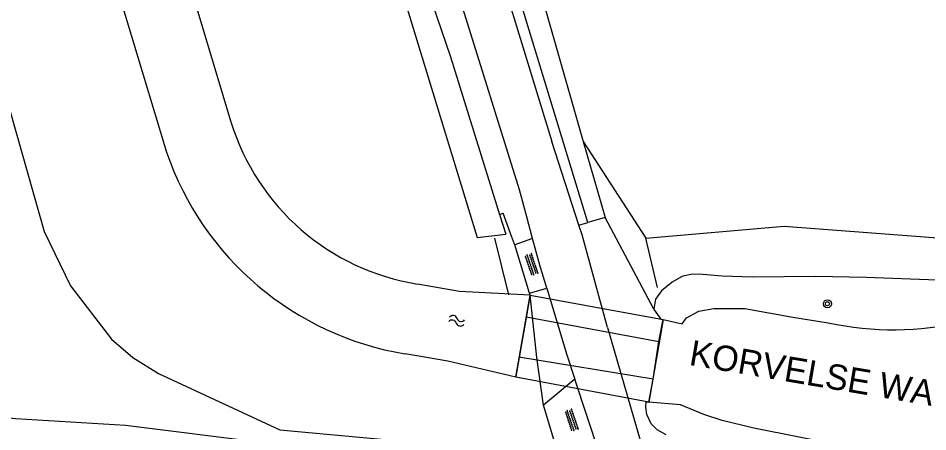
# Model space of a CAD drawing. Extents: x 135999 to 138000, y 396000 to 398501.
# Drawn here: x 136678.3 to 136768.1, y 396574.3 to 396615.1 of the extents above; entities that cross this region are included whole.
import ezdxf

# ---------------------------------------------------------------- set-up
doc = ezdxf.new("R2010")
doc.units = 0
for name, color, linetype in [('gg-afsc-draadraster', 7, 'Continuous'), ('gg-afsc-erfafscheiding', 7, 'Continuous'), ('gg-afsc-faunaraster', 7, 'Continuous'), ('gg-afsc-hekwerk', 7, 'Continuous'), ('gg-afsc-muur', 7, 'Continuous'), ('gg-anno-naam water', 7, 'Continuous'), ('gg-knt-bronhoudergrens', 7, 'Continuous'), ('gg-knt-onverhard', 7, 'Continuous'), ('gg-knt-verharding', 7, 'Continuous'), ('gg-kntw-beschoeiing', 7, 'Continuous'), ('gg-kntw-bovenkant insteek waterloop', 7, 'Continuous'), ('gg-kntw-waterlijn', 7, 'Continuous'), ('gg-kwrk-duiker nz buis', 7, 'Continuous'), ('gg-kwrk-duiker nz vlak', 7, 'Continuous'), ('gt-grn-groengrens', 7, 'Continuous'), ('gt-symb-boom', 7, 'Continuous'), ('gt-symb-overige verharding', 7, 'Continuous'), ('gt-symb-watersymbool', 7, 'Continuous'), ('gx-grn-maaiveld', 7, 'Continuous')]:
    doc.layers.add(name, color=color, linetype=linetype)

# ---------------------------------------------------------------- blocks, each defined once
blk = doc.blocks.new('gt0-OVH')
at = {"layer": 'gt-symb-overige verharding'}
for points in [[(-0.972, 0.298), (-0.967, 0.308), (-0.965, 0.319), (-0.966, 0.33), (-0.971, 0.34), (-0.978, 0.348), (-0.988, 0.353), (-0.999, 0.355), (-1.01, 0.354), (-1.02, 0.349), (-1.028, 0.342), (-1.033, 0.332), (-1.035, 0.321), (-1.034, 0.31), (-1.029, 0.3), (-1.022, 0.292), (-1.012, 0.287), (-1.001, 0.285), (-0.99, 0.286), (-0.98, 0.291)], [(-0.872, 0.106), (-0.867, 0.116), (-0.865, 0.126), (-0.866, 0.137), (-0.871, 0.147), (-0.878, 0.156), (-0.888, 0.161), (-0.899, 0.163), (-0.91, 0.162), (-0.92, 0.157), (-0.928, 0.15), (-0.933, 0.14), (-0.935, 0.129), (-0.934, 0.118), (-0.929, 0.108), (-0.922, 0.1), (-0.912, 0.095), (-0.901, 0.092), (-0.89, 0.094), (-0.88, 0.098)], [(-0.772, 0.298), (-0.767, 0.308), (-0.765, 0.319), (-0.766, 0.33), (-0.771, 0.34), (-0.778, 0.348), (-0.788, 0.353), (-0.799, 0.355), (-0.81, 0.354), (-0.82, 0.349), (-0.828, 0.342), (-0.833, 0.332), (-0.835, 0.321), (-0.834, 0.31), (-0.829, 0.3), (-0.822, 0.292), (-0.812, 0.287), (-0.801, 0.285), (-0.79, 0.286), (-0.78, 0.291)], [(-0.672, 0.106), (-0.667, 0.116), (-0.665, 0.126), (-0.666, 0.137), (-0.671, 0.147), (-0.678, 0.156), (-0.688, 0.161), (-0.699, 0.163), (-0.71, 0.162), (-0.72, 0.157), (-0.728, 0.15), (-0.733, 0.14), (-0.735, 0.129), (-0.734, 0.118), (-0.729, 0.108), (-0.722, 0.1), (-0.712, 0.095), (-0.701, 0.092), (-0.69, 0.094), (-0.68, 0.098)], [(-0.572, 0.298), (-0.567, 0.308), (-0.565, 0.319), (-0.566, 0.33), (-0.571, 0.34), (-0.578, 0.348), (-0.588, 0.353), (-0.599, 0.355), (-0.61, 0.354), (-0.62, 0.349), (-0.628, 0.342), (-0.633, 0.332), (-0.635, 0.321), (-0.634, 0.31), (-0.629, 0.3), (-0.622, 0.292), (-0.612, 0.287), (-0.601, 0.285), (-0.59, 0.286), (-0.58, 0.291)], [(-0.472, 0.106), (-0.467, 0.116), (-0.465, 0.126), (-0.466, 0.137), (-0.471, 0.147), (-0.478, 0.156), (-0.488, 0.161), (-0.499, 0.163), (-0.51, 0.162), (-0.52, 0.157), (-0.528, 0.15), (-0.533, 0.14), (-0.535, 0.129), (-0.534, 0.118), (-0.529, 0.108), (-0.522, 0.1), (-0.512, 0.095), (-0.501, 0.092), (-0.49, 0.094), (-0.48, 0.098)], [(-0.372, 0.298), (-0.367, 0.308), (-0.365, 0.319), (-0.366, 0.33), (-0.371, 0.34), (-0.378, 0.348), (-0.388, 0.353), (-0.399, 0.355), (-0.41, 0.354), (-0.42, 0.349), (-0.428, 0.342), (-0.433, 0.332), (-0.435, 0.321), (-0.434, 0.31), (-0.429, 0.3), (-0.422, 0.292), (-0.412, 0.287), (-0.401, 0.285), (-0.39, 0.286), (-0.38, 0.291)], [(-0.272, 0.106), (-0.267, 0.116), (-0.265, 0.126), (-0.266, 0.137), (-0.271, 0.147), (-0.278, 0.156), (-0.288, 0.161), (-0.299, 0.163), (-0.31, 0.162), (-0.32, 0.157), (-0.328, 0.15), (-0.333, 0.14), (-0.335, 0.129), (-0.334, 0.118), (-0.329, 0.108), (-0.322, 0.1), (-0.312, 0.095), (-0.301, 0.092), (-0.29, 0.094), (-0.28, 0.098)], [(-0.172, 0.298), (-0.167, 0.308), (-0.165, 0.319), (-0.166, 0.33), (-0.171, 0.34), (-0.178, 0.348), (-0.188, 0.353), (-0.199, 0.355), (-0.21, 0.354), (-0.22, 0.349), (-0.228, 0.342), (-0.233, 0.332), (-0.235, 0.321), (-0.234, 0.31), (-0.229, 0.3), (-0.222, 0.292), (-0.212, 0.287), (-0.201, 0.285), (-0.19, 0.286), (-0.18, 0.291)], [(-0.072, 0.106), (-0.067, 0.116), (-0.065, 0.126), (-0.066, 0.137), (-0.071, 0.147), (-0.078, 0.156), (-0.088, 0.161), (-0.099, 0.163), (-0.11, 0.162), (-0.12, 0.157), (-0.128, 0.15), (-0.133, 0.14), (-0.135, 0.129), (-0.134, 0.118), (-0.129, 0.108), (-0.122, 0.1), (-0.112, 0.095), (-0.101, 0.092), (-0.09, 0.094), (-0.08, 0.098)], [(0.028, 0.298), (0.033, 0.308), (0.035, 0.319), (0.034, 0.33), (0.029, 0.34), (0.022, 0.348), (0.012, 0.353), (0.001, 0.355), (-0.01, 0.354), (-0.02, 0.349), (-0.028, 0.342), (-0.033, 0.332), (-0.035, 0.321), (-0.034, 0.31), (-0.029, 0.3), (-0.022, 0.292), (-0.012, 0.287), (-0.001, 0.285), (0.01, 0.286), (0.02, 0.291)], [(0.128, 0.106), (0.133, 0.116), (0.135, 0.126), (0.134, 0.137), (0.129, 0.147), (0.122, 0.156), (0.112, 0.161), (0.101, 0.163), (0.09, 0.162), (0.08, 0.157), (0.072, 0.15), (0.067, 0.14), (0.065, 0.129), (0.066, 0.118), (0.071, 0.108), (0.078, 0.1), (0.088, 0.095), (0.099, 0.092), (0.11, 0.094), (0.12, 0.098)], [(0.228, 0.298), (0.233, 0.308), (0.235, 0.319), (0.234, 0.33), (0.229, 0.34), (0.222, 0.348), (0.212, 0.353), (0.201, 0.355), (0.19, 0.354), (0.18, 0.349), (0.172, 0.342), (0.167, 0.332), (0.165, 0.321), (0.166, 0.31), (0.171, 0.3), (0.178, 0.292), (0.188, 0.287), (0.199, 0.285), (0.21, 0.286), (0.22, 0.291)], [(0.328, 0.106), (0.333, 0.116), (0.335, 0.126), (0.334, 0.137), (0.329, 0.147), (0.322, 0.156), (0.312, 0.161), (0.301, 0.163), (0.29, 0.162), (0.28, 0.157), (0.272, 0.15), (0.267, 0.14), (0.265, 0.129), (0.266, 0.118), (0.271, 0.108), (0.278, 0.1), (0.288, 0.095), (0.299, 0.092), (0.31, 0.094), (0.32, 0.098)], [(0.428, 0.298), (0.433, 0.308), (0.435, 0.319), (0.434, 0.33), (0.429, 0.34), (0.422, 0.348), (0.412, 0.353), (0.401, 0.355), (0.39, 0.354), (0.38, 0.349), (0.372, 0.342), (0.367, 0.332), (0.365, 0.321), (0.366, 0.31), (0.371, 0.3), (0.378, 0.292), (0.388, 0.287), (0.399, 0.285), (0.41, 0.286), (0.42, 0.291)], [(0.528, 0.106), (0.533, 0.116), (0.535, 0.126), (0.534, 0.137), (0.529, 0.147), (0.522, 0.156), (0.512, 0.161), (0.501, 0.163), (0.49, 0.162), (0.48, 0.157), (0.472, 0.15), (0.467, 0.14), (0.465, 0.129), (0.466, 0.118), (0.471, 0.108), (0.478, 0.1), (0.488, 0.095), (0.499, 0.092), (0.51, 0.094), (0.52, 0.098)], [(0.628, 0.298), (0.633, 0.308), (0.635, 0.319), (0.634, 0.33), (0.629, 0.34), (0.622, 0.348), (0.612, 0.353), (0.601, 0.355), (0.59, 0.354), (0.58, 0.349), (0.572, 0.342), (0.567, 0.332), (0.565, 0.321), (0.566, 0.31), (0.571, 0.3), (0.578, 0.292), (0.588, 0.287), (0.599, 0.285), (0.61, 0.286), (0.62, 0.291)], [(0.728, 0.106), (0.733, 0.116), (0.735, 0.126), (0.734, 0.137), (0.729, 0.147), (0.722, 0.156), (0.712, 0.161), (0.701, 0.163), (0.69, 0.162), (0.68, 0.157), (0.672, 0.15), (0.667, 0.14), (0.665, 0.129), (0.666, 0.118), (0.671, 0.108), (0.678, 0.1), (0.688, 0.095), (0.699, 0.092), (0.71, 0.094), (0.72, 0.098)], [(0.828, 0.298), (0.833, 0.308), (0.835, 0.319), (0.834, 0.33), (0.829, 0.34), (0.822, 0.348), (0.812, 0.353), (0.801, 0.355), (0.79, 0.354), (0.78, 0.349), (0.772, 0.342), (0.767, 0.332), (0.765, 0.321), (0.766, 0.31), (0.771, 0.3), (0.778, 0.292), (0.788, 0.287), (0.799, 0.285), (0.81, 0.286), (0.82, 0.291)], [(0.928, 0.106), (0.933, 0.116), (0.935, 0.126), (0.934, 0.137), (0.929, 0.147), (0.922, 0.156), (0.912, 0.161), (0.901, 0.163), (0.89, 0.162), (0.88, 0.157), (0.872, 0.15), (0.867, 0.14), (0.865, 0.129), (0.866, 0.118), (0.871, 0.108), (0.878, 0.1), (0.888, 0.095), (0.899, 0.092), (0.91, 0.094), (0.92, 0.098)], [(1.028, 0.298), (1.033, 0.308), (1.035, 0.319), (1.034, 0.33), (1.029, 0.34), (1.022, 0.348), (1.012, 0.353), (1.001, 0.355), (0.99, 0.354), (0.98, 0.349), (0.972, 0.342), (0.967, 0.332), (0.965, 0.321), (0.966, 0.31), (0.971, 0.3), (0.978, 0.292), (0.988, 0.287), (0.999, 0.285), (1.01, 0.286), (1.02, 0.291)], [(-0.972, -0.142), (-0.967, -0.132), (-0.965, -0.121), (-0.966, -0.11), (-0.971, -0.1), (-0.978, -0.092), (-0.988, -0.087), (-0.999, -0.085), (-1.01, -0.086), (-1.02, -0.091), (-1.028, -0.098), (-1.033, -0.108), (-1.035, -0.119), (-1.034, -0.13), (-1.029, -0.14), (-1.022, -0.148), (-1.012, -0.153), (-1.001, -0.155), (-0.99, -0.154), (-0.98, -0.149)], [(-0.872, -0.334), (-0.867, -0.324), (-0.865, -0.314), (-0.866, -0.303), (-0.871, -0.293), (-0.878, -0.284), (-0.888, -0.279), (-0.899, -0.277), (-0.91, -0.278), (-0.92, -0.283), (-0.928, -0.29), (-0.933, -0.3), (-0.935, -0.311), (-0.934, -0.322), (-0.929, -0.332), (-0.922, -0.34), (-0.912, -0.345), (-0.901, -0.348), (-0.89, -0.346), (-0.88, -0.342)], [(-0.772, -0.142), (-0.767, -0.132), (-0.765, -0.121), (-0.766, -0.11), (-0.771, -0.1), (-0.778, -0.092), (-0.788, -0.087), (-0.799, -0.085), (-0.81, -0.086), (-0.82, -0.091), (-0.828, -0.098), (-0.833, -0.108), (-0.835, -0.119), (-0.834, -0.13), (-0.829, -0.14), (-0.822, -0.148), (-0.812, -0.153), (-0.801, -0.155), (-0.79, -0.154), (-0.78, -0.149)], [(-0.672, -0.334), (-0.667, -0.324), (-0.665, -0.314), (-0.666, -0.303), (-0.671, -0.293), (-0.678, -0.284), (-0.688, -0.279), (-0.699, -0.277), (-0.71, -0.278), (-0.72, -0.283), (-0.728, -0.29), (-0.733, -0.3), (-0.735, -0.311), (-0.734, -0.322), (-0.729, -0.332), (-0.722, -0.34), (-0.712, -0.345), (-0.701, -0.348), (-0.69, -0.346), (-0.68, -0.342)], [(-0.572, -0.142), (-0.567, -0.132), (-0.565, -0.121), (-0.566, -0.11), (-0.571, -0.1), (-0.578, -0.092), (-0.588, -0.087), (-0.599, -0.085), (-0.61, -0.086), (-0.62, -0.091), (-0.628, -0.098), (-0.633, -0.108), (-0.635, -0.119), (-0.634, -0.13), (-0.629, -0.14), (-0.622, -0.148), (-0.612, -0.153), (-0.601, -0.155), (-0.59, -0.154), (-0.58, -0.149)], [(-0.472, -0.334), (-0.467, -0.324), (-0.465, -0.314), (-0.466, -0.303), (-0.471, -0.293), (-0.478, -0.284), (-0.488, -0.279), (-0.499, -0.277), (-0.51, -0.278), (-0.52, -0.283), (-0.528, -0.29), (-0.533, -0.3), (-0.535, -0.311), (-0.534, -0.322), (-0.529, -0.332), (-0.522, -0.34), (-0.512, -0.345), (-0.501, -0.348), (-0.49, -0.346), (-0.48, -0.342)], [(-0.372, -0.142), (-0.367, -0.132), (-0.365, -0.121), (-0.366, -0.11), (-0.371, -0.1), (-0.378, -0.092), (-0.388, -0.087), (-0.399, -0.085), (-0.41, -0.086), (-0.42, -0.091), (-0.428, -0.098), (-0.433, -0.108), (-0.435, -0.119), (-0.434, -0.13), (-0.429, -0.14), (-0.422, -0.148), (-0.412, -0.153), (-0.401, -0.155), (-0.39, -0.154), (-0.38, -0.149)], [(-0.272, -0.334), (-0.267, -0.324), (-0.265, -0.314), (-0.266, -0.303), (-0.271, -0.293), (-0.278, -0.284), (-0.288, -0.279), (-0.299, -0.277), (-0.31, -0.278), (-0.32, -0.283), (-0.328, -0.29), (-0.333, -0.3), (-0.335, -0.311), (-0.334, -0.322), (-0.329, -0.332), (-0.322, -0.34), (-0.312, -0.345), (-0.301, -0.348), (-0.29, -0.346), (-0.28, -0.342)], [(-0.172, -0.142), (-0.167, -0.132), (-0.165, -0.121), (-0.166, -0.11), (-0.171, -0.1), (-0.178, -0.092), (-0.188, -0.087), (-0.199, -0.085), (-0.21, -0.086), (-0.22, -0.091), (-0.228, -0.098), (-0.233, -0.108), (-0.235, -0.119), (-0.234, -0.13), (-0.229, -0.14), (-0.222, -0.148), (-0.212, -0.153), (-0.201, -0.155), (-0.19, -0.154), (-0.18, -0.149)], [(-0.072, -0.334), (-0.067, -0.324), (-0.065, -0.314), (-0.066, -0.303), (-0.071, -0.293), (-0.078, -0.284), (-0.088, -0.279), (-0.099, -0.277), (-0.11, -0.278), (-0.12, -0.283), (-0.128, -0.29), (-0.133, -0.3), (-0.135, -0.311), (-0.134, -0.322), (-0.129, -0.332), (-0.122, -0.34), (-0.112, -0.345), (-0.101, -0.348), (-0.09, -0.346), (-0.08, -0.342)], [(0.028, -0.142), (0.033, -0.132), (0.035, -0.121), (0.034, -0.11), (0.029, -0.1), (0.022, -0.092), (0.012, -0.087), (0.001, -0.085), (-0.01, -0.086), (-0.02, -0.091), (-0.028, -0.098), (-0.033, -0.108), (-0.035, -0.119), (-0.034, -0.13), (-0.029, -0.14), (-0.022, -0.148), (-0.012, -0.153), (-0.001, -0.155), (0.01, -0.154), (0.02, -0.149)], [(0.128, -0.334), (0.133, -0.324), (0.135, -0.314), (0.134, -0.303), (0.129, -0.293), (0.122, -0.284), (0.112, -0.279), (0.101, -0.277), (0.09, -0.278), (0.08, -0.283), (0.072, -0.29), (0.067, -0.3), (0.065, -0.311), (0.066, -0.322), (0.071, -0.332), (0.078, -0.34), (0.088, -0.345), (0.099, -0.348), (0.11, -0.346), (0.12, -0.342)], [(0.228, -0.142), (0.233, -0.132), (0.235, -0.121), (0.234, -0.11), (0.229, -0.1), (0.222, -0.092), (0.212, -0.087), (0.201, -0.085), (0.19, -0.086), (0.18, -0.091), (0.172, -0.098), (0.167, -0.108), (0.165, -0.119), (0.166, -0.13), (0.171, -0.14), (0.178, -0.148), (0.188, -0.153), (0.199, -0.155), (0.21, -0.154), (0.22, -0.149)], [(0.328, -0.334), (0.333, -0.324), (0.335, -0.314), (0.334, -0.303), (0.329, -0.293), (0.322, -0.284), (0.312, -0.279), (0.301, -0.277), (0.29, -0.278), (0.28, -0.283), (0.272, -0.29), (0.267, -0.3), (0.265, -0.311), (0.266, -0.322), (0.271, -0.332), (0.278, -0.34), (0.288, -0.345), (0.299, -0.348), (0.31, -0.346), (0.32, -0.342)], [(0.428, -0.142), (0.433, -0.132), (0.435, -0.121), (0.434, -0.11), (0.429, -0.1), (0.422, -0.092), (0.412, -0.087), (0.401, -0.085), (0.39, -0.086), (0.38, -0.091), (0.372, -0.098), (0.367, -0.108), (0.365, -0.119), (0.366, -0.13), (0.371, -0.14), (0.378, -0.148), (0.388, -0.153), (0.399, -0.155), (0.41, -0.154), (0.42, -0.149)], [(0.528, -0.334), (0.533, -0.324), (0.535, -0.314), (0.534, -0.303), (0.529, -0.293), (0.522, -0.284), (0.512, -0.279), (0.501, -0.277), (0.49, -0.278), (0.48, -0.283), (0.472, -0.29), (0.467, -0.3), (0.465, -0.311), (0.466, -0.322), (0.471, -0.332), (0.478, -0.34), (0.488, -0.345), (0.499, -0.348), (0.51, -0.346), (0.52, -0.342)], [(0.628, -0.142), (0.633, -0.132), (0.635, -0.121), (0.634, -0.11), (0.629, -0.1), (0.622, -0.092), (0.612, -0.087), (0.601, -0.085), (0.59, -0.086), (0.58, -0.091), (0.572, -0.098), (0.567, -0.108), (0.565, -0.119), (0.566, -0.13), (0.571, -0.14), (0.578, -0.148), (0.588, -0.153), (0.599, -0.155), (0.61, -0.154), (0.62, -0.149)], [(0.728, -0.334), (0.733, -0.324), (0.735, -0.314), (0.734, -0.303), (0.729, -0.293), (0.722, -0.284), (0.712, -0.279), (0.701, -0.277), (0.69, -0.278), (0.68, -0.283), (0.672, -0.29), (0.667, -0.3), (0.665, -0.311), (0.666, -0.322), (0.671, -0.332), (0.678, -0.34), (0.688, -0.345), (0.699, -0.348), (0.71, -0.346), (0.72, -0.342)], [(0.828, -0.142), (0.833, -0.132), (0.835, -0.121), (0.834, -0.11), (0.829, -0.1), (0.822, -0.092), (0.812, -0.087), (0.801, -0.085), (0.79, -0.086), (0.78, -0.091), (0.772, -0.098), (0.767, -0.108), (0.765, -0.119), (0.766, -0.13), (0.771, -0.14), (0.778, -0.148), (0.788, -0.153), (0.799, -0.155), (0.81, -0.154), (0.82, -0.149)], [(0.928, -0.334), (0.933, -0.324), (0.935, -0.314), (0.934, -0.303), (0.929, -0.293), (0.922, -0.284), (0.912, -0.279), (0.901, -0.277), (0.89, -0.278), (0.88, -0.283), (0.872, -0.29), (0.867, -0.3), (0.865, -0.311), (0.866, -0.322), (0.871, -0.332), (0.878, -0.34), (0.888, -0.345), (0.899, -0.348), (0.91, -0.346), (0.92, -0.342)], [(1.028, -0.142), (1.033, -0.132), (1.035, -0.121), (1.034, -0.11), (1.029, -0.1), (1.022, -0.092), (1.012, -0.087), (1.001, -0.085), (0.99, -0.086), (0.98, -0.091), (0.972, -0.098), (0.967, -0.108), (0.965, -0.119), (0.966, -0.13), (0.971, -0.14), (0.978, -0.148), (0.988, -0.153), (0.999, -0.155), (1.01, -0.154), (1.02, -0.149)]]:
    blk.add_lwpolyline(points, close=True, dxfattribs=at)
blk = doc.blocks.new('gt0-BOOM')
at = {"layer": 'gt-symb-boom'}
for radius in [0.4, 0.2]:
    blk.add_circle((0, 0), radius, dxfattribs=at)
blk = doc.blocks.new('gt0-WA')
at = {"layer": 'gt-symb-watersymbool'}
for centre, start, end in [((-0.323, 0.022), 28.07249, 151.92751), ((0.427, 0.422), 208.07248, 331.92751), ((-0.323, -0.428), 28.07249, 151.92751), ((0.427, -0.028), 208.07248, 331.92751)]:
    blk.add_arc(centre, 0.425, start, end, dxfattribs=at)

msp = doc.modelspace()

# ---------------------------------------------------------------- linework, layer by layer
at = {"layer": 'gg-afsc-draadraster'}
for p, q in [((136726.889, 396593.884), (136726.155, 396595.873)), ((136727.279, 396592.829), (136726.889, 396593.884)), ((136728.818, 396587.778), (136728.784, 396587.965))]:
    msp.add_line(p, q, dxfattribs=at)
msp.add_lwpolyline([(136730.147, 396576.906), (136729.488, 396581.616), (136728.818, 396587.778)], dxfattribs=at)
at = {"layer": 'gg-afsc-erfafscheiding'}
msp.add_line((136741.393, 396588.549), (136740.226, 396593.402), dxfattribs=at)
at = {"layer": 'gg-afsc-faunaraster'}
msp.add_lwpolyline([(136550.316, 396664.161), (136603.929, 396670.667), (136624.808, 396673.004), (136630.395, 396673.561), (136635.871, 396673.305), (136642.208, 396672.19), (136648.47, 396670.351), (136651.008, 396668.743), (136656.059, 396664.564), (136659.85, 396659.38), (136661.144, 396656.652), (136666.388, 396645.214), (136669.73, 396633.384), (136680.865, 396594.068), (136683.489, 396588.708), (136687.52, 396583.447), (136689.634, 396581.626), (136692.164, 396580.039), (136704.126, 396574.477), (136731.649, 396571.967)], dxfattribs=at)
at = {"layer": 'gg-afsc-hekwerk'}
for p, q in [((136727.302, 396592.754), (136727.279, 396592.829)), ((136728.775, 396587.993), (136727.302, 396592.754)), ((136728.784, 396587.965), (136728.775, 396587.993)), ((136731.649, 396571.967), (136730.147, 396576.906))]:
    msp.add_line(p, q, dxfattribs=at)
at = {"layer": 'gg-afsc-muur'}
msp.add_lwpolyline([(136740.53, 396577.231), (136740.949, 396579.494), (136741.526, 396583.213), (136741.95, 396585.371)], dxfattribs=at)
at = {"layer": 'gg-knt-bronhoudergrens'}
msp.add_line((136734.072, 396602.956), (136740.226, 396593.402), dxfattribs=at)
msp.add_lwpolyline([(136740.226, 396593.402), (136753.893, 396594.583), (136772.913, 396593.148), (136790.677, 396594.224), (136802.879, 396596.557), (136809.876, 396602.299), (136819.207, 396615.756), (136824.59, 396621.139), (136831.05, 396625.266), (136838.586, 396627.599), (136843.79, 396628.496), (136847.558, 396629.752), (136915.647, 396679.703)], dxfattribs=at)
at = {"layer": 'gg-knt-onverhard'}
for p, q in [((136729.066, 396593.374), (136727.302, 396592.754)), ((136728.775, 396587.993), (136730.456, 396588.479)), ((136733.226, 396579.493), (136730.147, 396576.906))]:
    msp.add_line(p, q, dxfattribs=at)
msp.add_lwpolyline([(136732.139, 396570.674), (136702.549, 396573.194), (136688.919, 396574.901), (136678.047, 396575.568), (136671.226, 396576.294)], dxfattribs=at)
at = {"layer": 'gg-knt-verharding'}
for p, q in [((136727.762, 396598.192), (136721.073, 396619.732)), ((136733.642, 396594.687), (136730.975, 396602.966)), ((136728.482, 396595.532), (136727.762, 396598.192)), ((136729.066, 396593.374), (136728.482, 396595.532)), ((136736.465, 396584.579), (136742.627, 396563.248)), ((136735.911, 396571.397), (136733.226, 396579.493))]:
    msp.add_line(p, q, dxfattribs=at)
for points in [[(136712.408, 396661.215), (136726.734, 396616.808), (136730.975, 396602.966)], [(136736.465, 396584.579), (136733.948, 396593.738), (136733.642, 396594.687)], [(136730.456, 396588.479), (136729.776, 396590.753), (136729.066, 396593.374)], [(136730.456, 396588.479), (136732.399, 396581.987), (136733.226, 396579.493)]]:
    msp.add_lwpolyline(points, dxfattribs=at)
at = {"layer": 'gg-kntw-beschoeiing'}
for p, q in [((136680.059, 396668.824), (136699.31, 396604.891)), ((136673.268, 396667.196), (136692.95, 396601.911)), ((136728.725, 396587.245), (136727.425, 396579.76)), ((136728.818, 396587.778), (136728.725, 396587.245)), ((136727.425, 396579.76), (136727.41, 396579.671))]:
    msp.add_line(p, q, dxfattribs=at)
for points in [[(136728.818, 396587.778), (136721.86, 396588.141), (136717.725, 396588.882)], [(136727.41, 396579.671), (136720.71, 396581.281), (136716.494, 396581.992)]]:
    msp.add_lwpolyline(points, dxfattribs=at)
for centre, radius, start, end in [((136721.366, 396611.666), 23.073, 197.07479, 260.92137), ((136721.407, 396611.673), 30.085, 198.93482, 260.60054)]:
    msp.add_arc(centre, radius, start, end, dxfattribs=at)
at = {"layer": 'gg-kntw-bovenkant insteek waterloop'}
for p, q in [((136716.434, 396616.989), (136723.591, 396593.475)), ((136734.072, 396602.956), (136736.211, 396595.44)), ((136725.81, 396595.766), (136726.414, 396593.825)), ((136736.211, 396595.44), (136734.522, 396594.945)), ((136723.591, 396593.475), (136726.414, 396593.825))]:
    msp.add_line(p, q, dxfattribs=at)
for points in [[(136734.522, 396594.945), (136726.477, 396621.345), (136713.148, 396662.724), (136715.63, 396663.54)], [(136715.63, 396663.54), (136722.593, 396642.721), (136729.402, 396619.365), (136734.072, 396602.956)], [(136717.51, 396621.393), (136719.166, 396616.631), (136720.968, 396611.332), (136725.81, 396595.766)], [(136798.851, 396590.555), (136798.4, 396590.433), (136797.245, 396590.297), (136796.308, 396590.173), (136790.361, 396589.489), (136787.371, 396589.26), (136785.374, 396589.149), (136781.539, 396589.028), (136778.538, 396589.013), (136772.492, 396589.138), (136761.982, 396589.535), (136756.983, 396589.628), (136750.81, 396589.572), (136747.778, 396589.674), (136745.85, 396589.836), (136744.83, 396589.844), (136743.877, 396589.652), (136743.694, 396589.577), (136742.851, 396589.053), (136741.776, 396588.198), (136741.183, 396587.404), (136741.026, 396586.408)], [(136741.026, 396586.408), (136741.045, 396586.327), (136741.734, 396585.43), (136741.95, 396585.371)], [(136742.239, 396573.985), (136741.371, 396574.485), (136740.773, 396575.091), (136740.321, 396575.986), (136740.237, 396576.721), (136740.284, 396577.254), (136740.53, 396577.231)]]:
    msp.add_lwpolyline(points, dxfattribs=at)
at = {"layer": 'gg-kntw-waterlijn'}
msp.add_lwpolyline([(136741.95, 396585.371), (136743.816, 396584.939), (136744.238, 396585.55), (136745.46, 396586.204), (136746.936, 396586.478), (136750.013, 396586.478), (136754.734, 396585.603), (136758.238, 396585.053)], dxfattribs=at)
msp.add_arc((136764.655, 396614.537), 30.174, 257.72142, 283.32411, dxfattribs=at)
at = {"layer": 'gg-kwrk-duiker nz buis'}
for p, q in [((136725.292, 396593.427), (136726.674, 396587.802)), ((136728.435, 396585.641), (136741.526, 396583.213)), ((136740.949, 396579.494), (136727.702, 396581.669))]:
    msp.add_line(p, q, dxfattribs=at)
at = {"layer": 'gg-kwrk-duiker nz vlak'}
msp.add_lwpolyline([(136728.819, 396587.776), (136741.948, 396585.37), (136740.529, 396577.233), (136727.412, 396579.681), (136728.819, 396587.776)], dxfattribs=at)
at = {"layer": 'gt-grn-groengrens'}
for p, q in [((136725.81, 396595.766), (136726.155, 396595.873)), ((136741.026, 396586.408), (136736.211, 396595.44)), ((136733.642, 396594.687), (136734.522, 396594.945))]:
    msp.add_line(p, q, dxfattribs=at)
at = {"layer": 'gx-grn-maaiveld'}
for points in [[(136740.53, 396577.231), (136740.949, 396579.494), (136741.526, 396583.213), (136741.95, 396585.371)], [(136766.877, 396568.683), (136766.874, 396568.962), (136766.822, 396569.209), (136766.418, 396570.134), (136765.76, 396570.909), (136764.821, 396571.532), (136763.885, 396571.901), (136762.777, 396572.205), (136759.839, 396572.879), (136750.9, 396574.665), (136747.758, 396575.403), (136745.955, 396575.993), (136743.67, 396576.943), (136740.53, 396577.231)]]:
    msp.add_lwpolyline(points, dxfattribs=at)

# ---------------------------------------------------------------- block references
at = {"layer": 'gt-symb-boom'}
msp.add_blockref('gt0-BOOM', (136758.154, 396586.934), dxfattribs=at)
at = {"layer": 'gt-symb-overige verharding'}
for p, rotation in [((136728.962, 396590.815), -71.22088212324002), ((136732.921, 396575.439), -71.22088212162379)]:
    msp.add_blockref('gt0-OVH', p, dxfattribs=dict(at, rotation=rotation))
at = {"layer": 'gt-symb-watersymbool', "rotation": -10.837910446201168}
msp.add_blockref('gt0-WA', (136721.525, 396585.266), dxfattribs=at)

# ---------------------------------------------------------------- texts
at = {"layer": 'gg-anno-naam water'}
msp.add_text('KORVELSE WATERLOOP', height=2.5, rotation=350.38697, dxfattribs=at).set_placement((136744.425, 396580.906))

doc.saveas('drawing.dxf')
